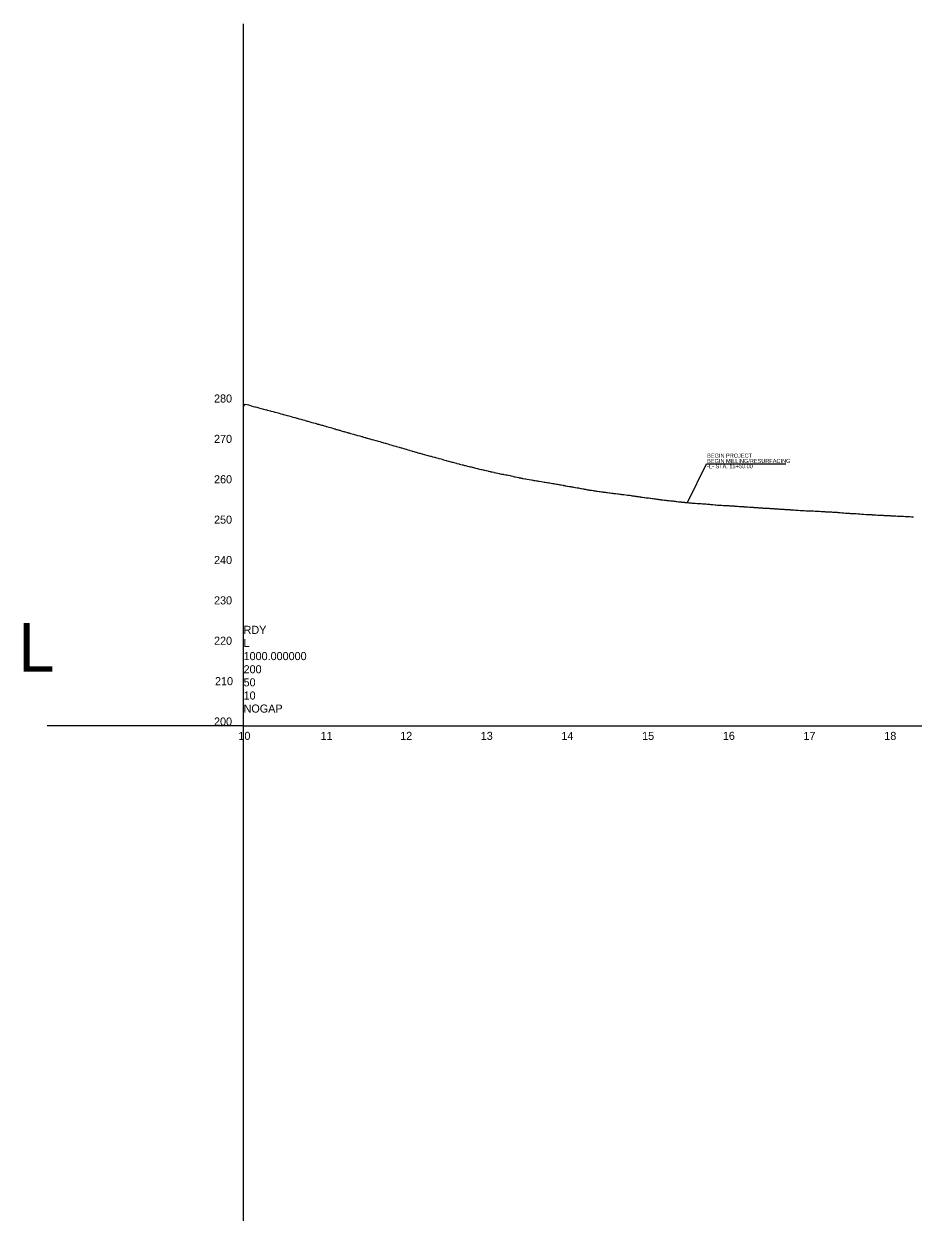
# Model space of a CAD drawing. Extents: x 2115752 to 2121174, y 562881 to 567245.
# Drawn here: x 2116424 to 2117526, y 565773 to 567245 of the extents above; entities that cross this region are included whole.
import ezdxf

# ---------------------------------------------------------------- set-up
doc = ezdxf.new("R2010")
doc.units = 0
for name, color, linetype in [('Exist Profile Cell', 7, 'Continuous'), ('Exist Vertical Profile Ground Line', 7, 'Continuous'), ('Exist Vertical Profile Horizontal Axis Label Major', 7, 'Continuous'), ('Exist Vertical Profile Vertical Axis Label', 7, 'Continuous'), ('Prop VPI Label', 7, 'Continuous'), ('Scratch_Level_1', 7, 'Continuous')]:
    doc.layers.add(name, color=color, linetype=linetype)

msp = doc.modelspace()

# ---------------------------------------------------------------- linework, layer by layer
at = {"layer": 'Exist Profile Cell'}
for q in [(2116696.3, 566625.8), (2121174.4, 566375.8), (2116696.3, 566375.8)]:
    msp.add_line((2116696.3, 566375.8), q, dxfattribs=at)
at = {"layer": 'Exist Vertical Profile Ground Line'}
for points in [[(2116696.3, 566771.3), (2116698.3, 566774.1), (2116700.9, 566773.5), (2116702.2, 566773.1), (2116703.5, 566772.7), (2116705.8, 566772.1), (2116706.1, 566772), (2116708.3, 566771.4), (2116710.4, 566770.8), (2116710.9, 566770.7), (2116712.9, 566770.2), (2116715.1, 566769.6), (2116717.7, 566768.9), (2116720, 566768.3), (2116720.6, 566768.1), (2116722.6, 566767.6), (2116723.1, 566767.5), (2116724.8, 566767), (2116725.1, 566766.9), (2116725.6, 566766.8), (2116727.6, 566766.3), (2116729.7, 566765.7), (2116730.2, 566765.5), (2116732.8, 566764.9), (2116735.1, 566764.3), (2116737.3, 566763.7), (2116737.6, 566763.6), (2116740.2, 566762.9), (2116742.5, 566762.3), (2116743, 566762.2), (2116744.6, 566761.7), (2116745.1, 566761.6), (2116745.5, 566761.5), (2116747.6, 566760.9), (2116750.2, 566760.2), (2116752.5, 566759.5), (2116755.1, 566758.8), (2116757.4, 566758.2), (2116759.9, 566757.5), (2116762.3, 566756.8), (2116763.2, 566756.6), (2116764.9, 566756.1), (2116765.3, 566756), (2116767.4, 566755.4), (2116769.9, 566754.7), (2116772, 566754.1), (2116772.5, 566754), (2116775.1, 566753.2), (2116776.3, 566752.9), (2116778.5, 566752.3), (2116779.6, 566752), (2116780.9, 566751.6), (2116782.9, 566751.1), (2116785.1, 566750.5), (2116786.3, 566750.1), (2116788, 566749.5), (2116789.5, 566749.2), (2116790.3, 566749), (2116792.7, 566748.3), (2116794.1, 566747.9), (2116795.2, 566747.5), (2116796, 566747.4), (2116798, 566746.8), (2116798.7, 566746.6), (2116799.2, 566746.5), (2116801.8, 566745.7), (2116802.5, 566745.5), (2116805.8, 566744.6), (2116807.5, 566744), (2116809.1, 566743.6), (2116809.6, 566743.5), (2116811.1, 566742.9), (2116812.4, 566742.6), (2116813.4, 566742.3), (2116814.6, 566741.9), (2116815.6, 566741.7), (2116817.3, 566741.2), (2116819, 566740.7), (2116819.9, 566740.4), (2116821.1, 566740.1), (2116821.7, 566739.9), (2116822.2, 566739.8), (2116825, 566739), (2116825.5, 566738.8), (2116827, 566738.4), (2116828.9, 566737.9), (2116832.5, 566736.9), (2116834.9, 566736.2), (2116835.2, 566736.1), (2116837.4, 566735.5), (2116840.1, 566734.7), (2116842.4, 566734.1), (2116843, 566733.9), (2116844.8, 566733.4), (2116846.7, 566732.9), (2116847.3, 566732.7), (2116847.9, 566732.5), (2116849, 566732.2), (2116849.9, 566732), (2116852.2, 566731.3), (2116852.5, 566731.2)], [(2116852.5, 566731.2), (2116855.1, 566730.5), (2116857.3, 566729.9), (2116860, 566729.1), (2116862.3, 566728.5), (2116862.7, 566728.3), (2116864.9, 566727.7), (2116867.2, 566727.1), (2116867.5, 566727), (2116869, 566726.5), (2116869.8, 566726.3), (2116871.5, 566725.8), (2116872.3, 566725.6), (2116875, 566724.8), (2116877.2, 566724.2), (2116879.8, 566723.4), (2116882.5, 566722.6), (2116884.8, 566722), (2116885.6, 566721.8), (2116887.3, 566721.3), (2116889, 566720.8), (2116889.7, 566720.6), (2116890.4, 566720.4), (2116891.5, 566720.1), (2116892.3, 566719.9), (2116894.3, 566719.3), (2116894.9, 566719.1), (2116897.1, 566718.4), (2116897.6, 566718.3), (2116899.7, 566717.7), (2116901.9, 566717.1), (2116902.4, 566716.9), (2116904.7, 566716.2), (2116905.2, 566716.1), (2116907.3, 566715.4), (2116909.6, 566714.7), (2116910, 566714.6), (2116911.4, 566714.2), (2116912.2, 566714), (2116914, 566713.5), (2116914.8, 566713.3), (2116915.7, 566713), (2116917.9, 566712.4), (2116918.3, 566712.3), (2116920.7, 566711.6), (2116921, 566711.5), (2116923.1, 566711), (2116925.1, 566710.5), (2116925.8, 566710.3), (2116927.7, 566709.8), (2116928.1, 566709.7), (2116928.8, 566709.5), (2116930.4, 566709), (2116930.7, 566709), (2116933, 566708.4), (2116933.3, 566708.3), (2116934.2, 566708), (2116935.6, 566707.7), (2116937.2, 566707.2), (2116938.2, 566706.9), (2116940.9, 566706.2), (2116943.2, 566705.5), (2116943.8, 566705.3), (2116945.7, 566704.8), (2116947.6, 566704.3), (2116948.1, 566704.1), (2116948.5, 566704), (2116950.3, 566703.6), (2116950.7, 566703.4), (2116951.9, 566703.1), (2116953.1, 566702.8), (2116954.3, 566702.4), (2116955.5, 566702.1), (2116956.6, 566701.8), (2116958.2, 566701.4), (2116959.9, 566700.9), (2116960.4, 566700.8), (2116960.8, 566700.7), (2116963.2, 566700.1), (2116963.6, 566699.9), (2116965.6, 566699.4), (2116967.5, 566699), (2116968, 566698.8), (2116968.3, 566698.8), (2116970.1, 566698.3), (2116970.6, 566698.2), (2116971.4, 566698), (2116972.9, 566697.6), (2116973.2, 566697.5), (2116975.4, 566696.9), (2116975.8, 566696.9), (2116976.9, 566696.6), (2116978.1, 566696.3), (2116979.5, 566696), (2116979.9, 566695.9), (2116980.7, 566695.7), (2116981.4, 566695.5), (2116983.4, 566695), (2116983.8, 566694.9), (2116984.1, 566694.9), (2116986.1, 566694.4)], [(2116986.1, 566694.4), (2116986.4, 566694.3), (2116986.9, 566694.2), (2116988.7, 566693.8), (2116990.7, 566693.3), (2116991.6, 566693.1), (2116993.2, 566692.7), (2116993.7, 566692.6), (2116994.6, 566692.4), (2116996.2, 566692), (2116996.8, 566691.9), (2116998.7, 566691.4), (2116999.3, 566691.3), (2117001.2, 566690.8), (2117002.3, 566690.6), (2117002.7, 566690.5), (2117003.7, 566690.2), (2117004.2, 566690.1), (2117006.2, 566689.7), (2117006.7, 566689.6), (2117008.7, 566689.1), (2117009.2, 566689), (2117011.4, 566688.5), (2117013.2, 566688.1), (2117013.7, 566688), (2117014.3, 566687.9), (2117015.9, 566687.6), (2117016.2, 566687.5), (2117016.6, 566687.5), (2117017.7, 566687.3), (2117018.7, 566687.2), (2117019.1, 566687.1), (2117021.3, 566686.7), (2117022.3, 566686.5), (2117023.8, 566686.2), (2117026.5, 566685.6), (2117027.4, 566685.3), (2117029.7, 566684.8), (2117030.1, 566684.7), (2117032.1, 566684.2), (2117032.5, 566684.1), (2117033.1, 566684), (2117035, 566683.5), (2117037.3, 566683.1), (2117037.7, 566683), (2117039.2, 566682.7), (2117039.9, 566682.6), (2117041.4, 566682.3), (2117041.9, 566682.2), (2117042.6, 566682.1), (2117044.8, 566681.8), (2117045.5, 566681.7), (2117047.6, 566681.4), (2117050, 566680.9), (2117052.6, 566680.4), (2117052.9, 566680.3), (2117054.7, 566680), (2117055.1, 566679.9), (2117056, 566679.7), (2117057.5, 566679.4), (2117059, 566679.2), (2117059.8, 566679.1), (2117060.5, 566679), (2117061.7, 566678.8), (2117062.5, 566678.7), (2117064.8, 566678.3), (2117067.2, 566677.9), (2117068.7, 566677.7), (2117070, 566677.5), (2117071.9, 566677.2), (2117072.3, 566677.1), (2117072.7, 566677.1), (2117074.5, 566676.8), (2117075, 566676.7), (2117075.8, 566676.6), (2117077.3, 566676.3), (2117078.9, 566676), (2117079.8, 566675.8), (2117080.3, 566675.8), (2117081.6, 566675.5), (2117082.4, 566675.3), (2117083.8, 566675.1), (2117084.3, 566675), (2117085, 566674.9), (2117087, 566674.5), (2117088.1, 566674.3), (2117089.7, 566674), (2117091.6, 566673.7), (2117092.1, 566673.6), (2117092.5, 566673.5), (2117094.3, 566673.2), (2117094.7, 566673.1), (2117095.3, 566673), (2117097, 566672.7), (2117097.4, 566672.7), (2117099.5, 566672.3), (2117100, 566672.2), (2117101.3, 566672), (2117102.2, 566671.9), (2117103.1, 566671.8), (2117104.1, 566671.6)], [(2117104.1, 566671.6), (2117104.9, 566671.4), (2117106.9, 566671), (2117107.5, 566671), (2117109.6, 566670.6), (2117110.8, 566670.4), (2117111.2, 566670.3), (2117112.3, 566670.1), (2117114.2, 566669.8), (2117115.1, 566669.6), (2117116.9, 566669.2), (2117117.3, 566669.1), (2117118.3, 566669), (2117119.8, 566668.7), (2117121.2, 566668.4), (2117122.1, 566668.2), (2117122.7, 566668.1), (2117123.9, 566667.9), (2117124.7, 566667.8), (2117126.5, 566667.5), (2117126.9, 566667.4), (2117127.4, 566667.4), (2117129.4, 566667), (2117130.4, 566666.9), (2117132.1, 566666.6), (2117133.5, 566666.5), (2117134.4, 566666.3), (2117134.9, 566666.2), (2117136.7, 566666), (2117137.2, 566665.9), (2117137.9, 566665.8), (2117139.5, 566665.6), (2117141.1, 566665.4), (2117141.9, 566665.3), (2117142.4, 566665.2), (2117143.8, 566665.1), (2117144.6, 566665), (2117145.8, 566664.8), (2117146.6, 566664.7), (2117147.3, 566664.6), (2117149.3, 566664.3), (2117149.8, 566664.3), (2117152, 566664), (2117153.1, 566663.9), (2117153.9, 566663.8), (2117154.7, 566663.6), (2117156.6, 566663.4), (2117157.1, 566663.3), (2117157.6, 566663.3), (2117159.3, 566663.1), (2117159.7, 566663), (2117160.6, 566662.9), (2117162.2, 566662.7), (2117163.7, 566662.5), (2117164.5, 566662.4), (2117165.2, 566662.3), (2117166.5, 566662.2), (2117167.2, 566662.1), (2117169.7, 566661.8), (2117171.9, 566661.5), (2117173.1, 566661.4), (2117174.6, 566661.2), (2117176.5, 566660.9), (2117177.4, 566660.7), (2117179.2, 566660.5), (2117179.7, 566660.4), (2117180.4, 566660.3), (2117182, 566660.1), (2117182.6, 566660), (2117183.1, 566659.9), (2117183.9, 566659.8), (2117185.4, 566659.6), (2117186.9, 566659.4), (2117187.9, 566659.2), (2117188.6, 566659.1), (2117189.6, 566659), (2117190.5, 566658.9), (2117192.5, 566658.6), (2117193.3, 566658.5), (2117195.2, 566658.2), (2117196, 566658.2), (2117196.3, 566658.1), (2117198, 566657.9), (2117199.8, 566657.6), (2117200.7, 566657.5), (2117202.5, 566657.3), (2117203, 566657.2), (2117203.8, 566657.2), (2117205.3, 566657), (2117205.7, 566656.9), (2117206.8, 566656.7), (2117208.2, 566656.5), (2117209.5, 566656.4), (2117210.5, 566656.2), (2117211.6, 566656.1), (2117212.3, 566656), (2117213.2, 566655.8), (2117215.6, 566655.5), (2117217.8, 566655.3), (2117218.7, 566655.2), (2117219, 566655.2)], [(2117219, 566655.2), (2117219.5, 566655.1), (2117220.6, 566655), (2117222.4, 566654.8), (2117223.4, 566654.7), (2117225.1, 566654.5), (2117225.6, 566654.5), (2117226.6, 566654.4), (2117228, 566654.2), (2117229.4, 566654), (2117230.4, 566653.9), (2117231.1, 566653.8), (2117232.1, 566653.7), (2117233, 566653.6), (2117235.1, 566653.3), (2117235.8, 566653.2), (2117237.7, 566653), (2117238.3, 566653), (2117238.9, 566652.9), (2117240.4, 566652.8), (2117242.3, 566652.6), (2117242.9, 566652.5), (2117243.3, 566652.5), (2117245, 566652.3), (2117245.5, 566652.3), (2117246.2, 566652.2), (2117247.7, 566652.1), (2117249.3, 566651.9), (2117250.2, 566651.9), (2117250.7, 566651.8), (2117252, 566651.7), (2117252.9, 566651.6), (2117254.1, 566651.5), (2117254.8, 566651.5), (2117255.6, 566651.4), (2117258, 566651.2), (2117260.3, 566651.1), (2117261.3, 566651), (2117262.1, 566651), (2117263, 566650.9), (2117264.9, 566650.8), (2117265.4, 566650.7), (2117265.9, 566650.7), (2117267.6, 566650.6), (2117268, 566650.5), (2117269, 566650.5), (2117270.4, 566650.3), (2117271.9, 566650.2), (2117272.8, 566650.1), (2117273.5, 566650.1), (2117274.7, 566649.9), (2117275.5, 566649.8), (2117277.7, 566649.7), (2117280.2, 566649.5), (2117281.3, 566649.4), (2117282.9, 566649.2), (2117284.8, 566649.1), (2117285.6, 566649), (2117287.5, 566648.9), (2117287.9, 566648.9), (2117288.6, 566648.9), (2117290.3, 566648.8), (2117291.9, 566648.8), (2117292.7, 566648.7), (2117293.1, 566648.7), (2117294.6, 566648.7), (2117295.4, 566648.6), (2117296.5, 566648.6), (2117297.4, 566648.5), (2117298.1, 566648.4), (2117300.1, 566648.3), (2117300.8, 566648.3), (2117302.8, 566648.1), (2117303.8, 566648), (2117304.2, 566648), (2117304.6, 566647.9), (2117305.5, 566647.8), (2117307.4, 566647.7), (2117307.9, 566647.7), (2117308.3, 566647.6), (2117308.7, 566647.6), (2117310.4, 566647.5), (2117310.9, 566647.5), (2117311.8, 566647.4), (2117313.3, 566647.3), (2117314.7, 566647.2), (2117315.7, 566647.2), (2117316.2, 566647.1), (2117317.5, 566647.1), (2117318.4, 566647), (2117320, 566646.9), (2117320.3, 566646.9), (2117321, 566646.8), (2117323.1, 566646.7), (2117323.8, 566646.6), (2117325.8, 566646.5), (2117327.7, 566646.4), (2117328.5, 566646.3), (2117330.4, 566646.2), (2117330.8, 566646.2), (2117331.4, 566646.2)], [(2117331.4, 566646.2), (2117333.1, 566646), (2117333.5, 566646), (2117334.3, 566645.9), (2117335.9, 566645.8), (2117337.5, 566645.7), (2117338.3, 566645.7), (2117339.2, 566645.6), (2117340.1, 566645.5), (2117340.9, 566645.5), (2117343.2, 566645.4), (2117343.7, 566645.3), (2117345.7, 566645.2), (2117346.5, 566645.1), (2117347.2, 566645.1), (2117348.4, 566645), (2117350.3, 566644.9), (2117350.8, 566644.8), (2117351.2, 566644.8), (2117353, 566644.7), (2117353.4, 566644.7), (2117354.1, 566644.6), (2117355.7, 566644.5), (2117357.4, 566644.4), (2117358.2, 566644.3), (2117358.8, 566644.3), (2117360, 566644.2), (2117360.8, 566644.2), (2117362.2, 566644.1), (2117362.9, 566644.1), (2117363.6, 566644), (2117365.6, 566643.9), (2117366.1, 566643.9), (2117366.6, 566643.8), (2117368.3, 566643.7), (2117370.3, 566643.6), (2117370.7, 566643.6), (2117371, 566643.6), (2117372.9, 566643.5), (2117373.3, 566643.4), (2117373.8, 566643.4), (2117375.6, 566643.3), (2117376, 566643.2), (2117378.1, 566643.1), (2117378.5, 566643.1), (2117380, 566643), (2117380.8, 566642.9), (2117381.5, 566642.9), (2117382.7, 566642.8), (2117383.5, 566642.7), (2117385.8, 566642.6), (2117388.2, 566642.5), (2117389.5, 566642.4), (2117390.9, 566642.3), (2117392.8, 566642.2), (2117393.6, 566642.2), (2117395.5, 566642.1), (2117395.9, 566642.1), (2117396.7, 566642.1), (2117398.3, 566642), (2117399.2, 566642), (2117399.7, 566641.9), (2117400.5, 566641.9), (2117402, 566641.9), (2117402.4, 566641.8), (2117404.5, 566641.7), (2117405.2, 566641.7), (2117405.8, 566641.7), (2117407.1, 566641.6), (2117408.9, 566641.5), (2117409.9, 566641.4), (2117411.9, 566641.3), (2117412.6, 566641.2), (2117414.5, 566641.1), (2117416.5, 566641), (2117417, 566640.9), (2117417.3, 566640.9), (2117419.1, 566640.8), (2117419.6, 566640.8), (2117420.1, 566640.8), (2117421.8, 566640.7), (2117422.3, 566640.7), (2117423.7, 566640.6), (2117424.8, 566640.6), (2117425.9, 566640.5), (2117427.1, 566640.5), (2117428.4, 566640.4), (2117429.8, 566640.4), (2117431.8, 566640.2), (2117432.4, 566640.1), (2117434.8, 566639.9), (2117435.4, 566639.8), (2117437.2, 566639.7), (2117439.1, 566639.5), (2117439.6, 566639.4), (2117440, 566639.4), (2117441.8, 566639.2), (2117442.2, 566639.2), (2117443.2, 566639.2), (2117444.6, 566639.1), (2117446, 566639)], [(2117446, 566639), (2117447, 566639), (2117447.7, 566638.9), (2117448.4, 566638.9), (2117449.7, 566638.8), (2117451.2, 566638.7), (2117451.7, 566638.7), (2117452.3, 566638.6), (2117454.7, 566638.5), (2117455.1, 566638.5), (2117457.1, 566638.4), (2117459.1, 566638.2), (2117459.8, 566638.1), (2117461.7, 566638), (2117462.1, 566637.9), (2117462.6, 566637.9), (2117464.4, 566637.8), (2117464.8, 566637.8), (2117467, 566637.6), (2117467.3, 566637.6), (2117468.6, 566637.6), (2117469.6, 566637.5), (2117470.4, 566637.5), (2117471.3, 566637.4), (2117472.2, 566637.4), (2117474.4, 566637.3), (2117474.9, 566637.2), (2117477.2, 566637.1), (2117477.7, 566637.1), (2117479.7, 566637), (2117481.7, 566636.8), (2117482.1, 566636.8), (2117482.4, 566636.8), (2117484.3, 566636.7), (2117484.7, 566636.7), (2117485.5, 566636.6), (2117487.1, 566636.5), (2117488.6, 566636.5), (2117489.6, 566636.4), (2117490.1, 566636.4), (2117491.2, 566636.3), (2117492.2, 566636.3), (2117494, 566636.2), (2117494.8, 566636.2), (2117497, 566636.1), (2117497.5, 566636), (2117499.6, 566636), (2117501.1, 566635.9), (2117501.5, 566635.9), (2117503.7, 566635.8), (2117504.3, 566635.7), (2117506.2, 566635.6), (2117508.1, 566635.5), (2117508.6, 566635.5), (2117509.2, 566635.5), (2117510.7, 566635.4), (2117511.2, 566635.4), (2117513.7, 566635.2), (2117516, 566635.1), (2117516.4, 566635), (2117518.6, 566634.9), (2117521.3, 566634.8), (2117523.6, 566634.7), (2117524, 566634.6), (2117526.1, 566634.6)]]:
    msp.add_lwpolyline(points, dxfattribs=at)
at = {"layer": 'Prop VPI Label'}
for p, q in [((2117246.3, 566652.2), (2117269.6, 566700.1)), ((2117269.6, 566700.1), (2117367.9, 566700.1))]:
    msp.add_line(p, q, dxfattribs=at)
at = {"layer": 'Scratch_Level_1'}
for p, q in [((2116696.3, 566375.8), (2116696.3, 567245.2)), ((2116696.3, 566375.8), (2116452.8, 566375.8)), ((2116696.3, 565506.4), (2116696.3, 566375.8)), ((2116696.3, 566327.9), (2116696.3, 566355.9))]:
    msp.add_line(p, q, dxfattribs=at)

# ---------------------------------------------------------------- texts
at = {"layer": 'Exist Profile Cell'}
for s, p in [('RDY', (2116696.3, 566489.6)), ('L', (2116696.3, 566473.3)), ('1000.000000', (2116696.3, 566457.1)), ('200', (2116696.3, 566440.8)), ('50', (2116696.3, 566424.6)), ('10', (2116696.3, 566408.3)), ('NOGAP', (2116696.3, 566392.1))]:
    msp.add_text(s, height=10, dxfattribs=at).set_placement(p)
at = {"layer": 'Exist Vertical Profile Horizontal Axis Label Major'}
for s, p in [('10', (2116689.9, 566358.3)), ('11', (2116791.7, 566358.3)), ('12', (2116890.3, 566358.3)), ('13', (2116990.1, 566358.3)), ('14', (2117090, 566358.3)), ('15', (2117190, 566358.3)), ('16', (2117290, 566358.3)), ('17', (2117389.8, 566358.3)), ('18', (2117490, 566358.3))]:
    msp.add_text(s, height=10, dxfattribs=at).set_placement(p)
at = {"layer": 'Exist Vertical Profile Vertical Axis Label'}
for s, height, p in [('280', 10, (2116659.7, 566776.1)), ('270', 10, (2116659.7, 566726.1)), ('260', 10, (2116659.7, 566676.1)), ('250', 10, (2116659.7, 566626.1)), ('240', 10, (2116659.7, 566576.1)), ('230', 10, (2116659.7, 566526.1)), ('L', 60, (2116417.4, 566442.9)), ('220', 10, (2116659.7, 566476.1)), ('210', 10, (2116660.9, 566426.1)), ('200', 10, (2116659.7, 566376.1))]:
    msp.add_text(s, height=height, dxfattribs=at).set_placement(p)
at = {"layer": 'Prop VPI Label'}
for s, p in [('BEGIN PROJECT', (2117270.5, 566707.9)), ('-L- STA. 15+50.00', (2117270.5, 566694.7)), ('BEGIN MILLING/RESURFACING', (2117270.5, 566701.3))]:
    msp.add_text(s, height=5, dxfattribs=at).set_placement(p)

doc.saveas('drawing.dxf')
